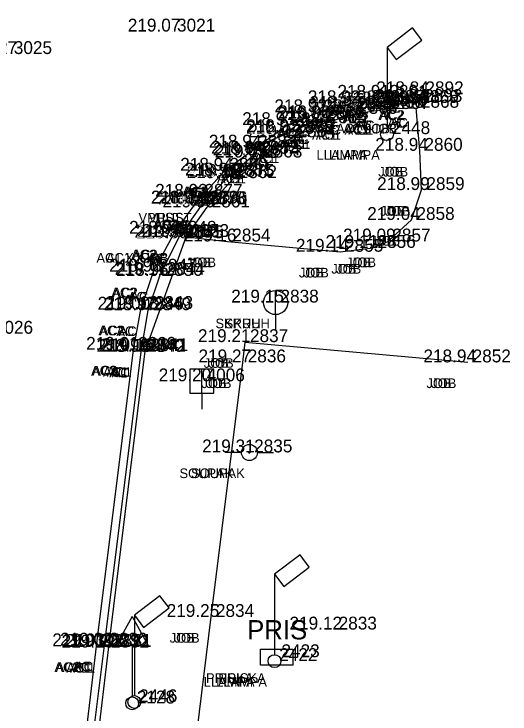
# Model space of a CAD drawing. Extents: x -471047 to -470889, y -1102859 to -1102000.
# Drawn here: x -470921.79 to -470906.35, y -1102184.25 to -1102162.47 of the extents above; entities that cross this region are included whole.
import ezdxf

# ---------------------------------------------------------------- set-up
doc = ezdxf.new("R2010")
doc.units = 0
for name, color, linetype in [('Vrstva 1', 7, 'Continuous'), ('Vrstva 11', 7, 'Continuous'), ('Vrstva 19', 7, 'Continuous'), ('Vrstva 23', 7, 'Continuous'), ('Vrstva 25', 7, 'Continuous'), ('Vrstva 30', 7, 'Continuous'), ('Vrstva 34', 7, 'Continuous'), ('Vrstva 35', 7, 'Continuous'), ('Vrstva 36', 7, 'Continuous'), ('Vrstva 38', 7, 'Continuous'), ('Vrstva 5', 7, 'Continuous'), ('Vrstva 7', 7, 'Continuous'), ('Vrstva 8', 7, 'Continuous')]:
    doc.layers.add(name, color=color, linetype=linetype)

msp = doc.modelspace()

# ---------------------------------------------------------------- linework, layer by layer
at = {"layer": 'Vrstva 1'}
for points in [[(-471040.344, -1102858.385), (-471031.676, -1102846.187), (-471026.357, -1102838.629), (-471023.212, -1102833.975), (-471019.21, -1102827.465), (-471016.861, -1102823.272), (-471013.099, -1102815.912), (-471010.824, -1102810.955), (-471007.329, -1102802.292), (-471005.34, -1102796.515), (-471002.842, -1102787.838), (-471001.3, -1102780.997), (-471000.19, -1102774.713), (-470999.247, -1102768.204), (-470998.794, -1102764.784), (-470997.199, -1102751.812), (-470994.899, -1102732.807), (-470992.551, -1102713.262), (-470990.326, -1102694.887), (-470988.122, -1102676.57), (-470985.812, -1102657.305), (-470983.537, -1102638.407), (-470981.386, -1102620.622), (-470979.843, -1102608.014), (-470976.377, -1102579.253), (-470972.945, -1102550.69), (-470970.475, -1102530.206), (-470967.905, -1102508.801), (-470965.053, -1102485.131), (-470962.734, -1102465.9), (-470960.173, -1102444.812), (-470957.795, -1102425.103), (-470954.965, -1102401.839), (-470953.834, -1102392.574), (-470952.33, -1102379.985), (-470950.744, -1102366.853), (-470948.978, -1102352.106), (-470947.037, -1102335.844), (-470944.949, -1102318.462), (-470944.013, -1102310.745), (-470942.39, -1102297.267), (-470939.519, -1102273.45), (-470937.593, -1102257.43), (-470936.064, -1102244.81), (-470934.114, -1102228.634), (-470931.621, -1102207.856), (-470929.536, -1102190.857), (-470926.572, -1102166.31), (-470924.91, -1102152.663), (-470923.413, -1102140.333), (-470921.923, -1102127.669), (-470921.155, -1102120.084), (-470920.446, -1102109.574), (-470919.912, -1102099.137), (-470919.63, -1102088.981), (-470919.523, -1102081.193), (-470919.563, -1102070.395), (-470919.714, -1102064.236), (-470920.134, -1102054.704), (-470920.462, -1102047.615), (-470920.599, -1102044.52), (-470920.743, -1102041.873), (-470921.125, -1102034.455), (-470921.774, -1102030.337), (-470922.418, -1102027.787), (-470923.734, -1102023.93), (-470924.872, -1102021.434), (-470926.752, -1102018.182), (-470927.953, -1102016.45), (-470929.616, -1102014.424), (-470932.252, -1102011.756), (-470935.111, -1102009.425), (-470938.391, -1102007.371), (-470942.651, -1102005.401)], [(-471041.328, -1102857.18), (-471032.144, -1102844.242), (-471027.583, -1102837.763), (-471024.388, -1102833.028), (-471020.451, -1102826.6), (-471018.089, -1102822.378), (-471014.542, -1102815.445), (-471012.233, -1102810.418), (-471009.247, -1102803.108), (-471006.795, -1102796.098), (-471004.315, -1102787.532), (-471002.782, -1102780.723), (-471001.674, -1102774.458), (-471000.75, -1102768.095), (-471000.28, -1102764.601), (-470998.692, -1102751.741), (-470996.378, -1102732.635), (-470994.028, -1102713.058), (-470991.808, -1102694.749), (-470989.616, -1102676.447), (-470987.284, -1102657.013), (-470985.031, -1102638.272), (-470982.87, -1102620.431), (-470981.334, -1102607.933), (-470977.881, -1102579.263), (-470974.429, -1102550.492), (-470971.964, -1102530.054), (-470969.391, -1102508.607), (-470966.54, -1102484.984), (-470964.231, -1102465.853), (-470961.679, -1102444.752), (-470959.304, -1102425.078), (-470956.455, -1102401.634), (-470955.339, -1102392.489), (-470953.812, -1102379.71), (-470952.249, -1102366.808), (-470950.479, -1102352.023), (-470948.536, -1102335.868), (-470946.426, -1102318.233), (-470945.493, -1102310.531), (-470943.864, -1102297.013), (-470940.984, -1102273.071), (-470939.078, -1102257.195), (-470937.559, -1102244.684), (-470935.592, -1102228.353), (-470933.101, -1102207.653), (-470931.011, -1102190.57), (-470928.046, -1102166.021), (-470926.409, -1102152.578), (-470924.898, -1102140.121), (-470923.427, -1102127.544), (-470922.647, -1102119.826), (-470921.919, -1102109.229), (-470921.42, -1102099.134), (-470921.127, -1102089.016), (-470921.023, -1102081.453), (-470921.061, -1102070.468), (-470921.209, -1102064.314), (-470921.666, -1102053.966), (-470922.156, -1102043.345), (-470922.299, -1102039.934), (-470922.637, -1102034.36), (-470923.091, -1102031.241), (-470923.847, -1102028.247), (-470925.083, -1102024.594), (-470926.222, -1102022.086), (-470928.04, -1102018.943), (-470929.138, -1102017.357), (-470930.929, -1102015.175), (-470933.062, -1102013.049), (-470936.379, -1102010.368), (-470939.169, -1102008.662), (-470942.899, -1102006.906), (-470945.661, -1102005.908)]]:
    msp.add_spline(points, degree=3, dxfattribs=at)
at = {"layer": 'Vrstva 11'}
for p, q in [((-470914.708, -1102176.114), (-470915.208, -1102176.114)), ((-470914.208, -1102176.114), (-470913.708, -1102176.114))]:
    msp.add_line(p, q, dxfattribs=at)
for radius in [0.25, 0.025]:
    msp.add_circle((-470914.458, -1102176.114), radius, dxfattribs=at)
at = {"layer": 'Vrstva 19'}
for p, q in [((-470918.107, -1102181.215), (-470918.607, -1102182.115)), ((-470918.107, -1102181.215), (-470917.607, -1102182.115)), ((-470917.607, -1102182.115), (-470918.607, -1102182.115)), ((-470918.107, -1102182.115), (-470918.107, -1102183.715))]:
    msp.add_line(p, q, dxfattribs=at)
msp.add_circle((-470918.107, -1102183.915), 0.2, dxfattribs=at)
at = {"layer": 'Vrstva 23'}
for p, q in [((-470909.38, -1102162.908), (-470910.175, -1102163.513)), ((-470909.09, -1102163.286), (-470909.38, -1102162.908)), ((-470909.888, -1102163.89), (-470909.09, -1102163.286)), ((-470910.175, -1102163.513), (-470910.175, -1102166.013)), ((-470910.175, -1102163.513), (-470909.888, -1102163.89)), ((-470912.884, -1102179.298), (-470913.679, -1102179.903)), ((-470912.594, -1102179.676), (-470912.884, -1102179.298)), ((-470913.392, -1102180.28), (-470912.594, -1102179.676)), ((-470913.679, -1102179.903), (-470913.679, -1102182.403)), ((-470913.679, -1102179.903), (-470913.392, -1102180.28)), ((-470917.245, -1102180.571), (-470918.04, -1102181.176)), ((-470916.955, -1102180.948), (-470917.245, -1102180.571)), ((-470917.752, -1102181.554), (-470916.955, -1102180.948)), ((-470918.04, -1102181.176), (-470918.04, -1102183.676)), ((-470918.04, -1102181.176), (-470917.752, -1102181.554))]:
    msp.add_line(p, q, dxfattribs=at)
msp.add_lwpolyline([(-470914.109, -1102182.231), (-470913.109, -1102182.231), (-470913.109, -1102182.731), (-470914.109, -1102182.731)], close=True, dxfattribs=at)
for centre in [(-470910.175, -1102166.213), (-470913.679, -1102182.603), (-470918.04, -1102183.876)]:
    msp.add_circle(centre, 0.2, dxfattribs=at)
at = {"layer": 'Vrstva 25'}
for p, q in [((-470916.26, -1102167.91), (-470916.26, -1102168.41)), ((-470915.76, -1102167.91), (-470916.26, -1102167.91)), ((-470915.76, -1102168.41), (-470915.76, -1102167.91)), ((-470916.26, -1102168.16), (-470915.76, -1102168.16)), ((-470916.26, -1102168.41), (-470915.76, -1102168.41)), ((-470913.643, -1102171.824), (-470913.643, -1102171.074)), ((-470913.643, -1102171.824), (-470913.643, -1102172.324))]:
    msp.add_line(p, q, dxfattribs=at)
msp.add_circle((-470913.643, -1102171.449), 0.375, dxfattribs=at)
at = {"layer": 'Vrstva 30'}
for p, q in [((-470916.315, -1102173.521), (-470916.315, -1102174.271)), ((-470915.565, -1102173.521), (-470916.315, -1102173.521)), ((-470915.94, -1102174.271), (-470915.94, -1102173.521)), ((-470915.565, -1102174.271), (-470915.565, -1102173.521)), ((-470916.315, -1102174.271), (-470915.565, -1102174.271)), ((-470915.94, -1102174.271), (-470915.94, -1102174.771))]:
    msp.add_line(p, q, dxfattribs=at)
at = {"layer": 'Vrstva 34'}
for p, q in [((-470916.86, -1102163.02), (-470916.86, -1102163.02)), ((-470910.25, -1102165.08), (-470910.25, -1102165.08)), ((-470909.13, -1102164.97), (-470909.13, -1102164.97)), ((-470911.26, -1102165.25), (-470911.26, -1102165.25)), ((-470910.21, -1102165.29), (-470910.21, -1102165.29)), ((-470909.28, -1102165.24), (-470909.28, -1102165.24)), ((-470909.17, -1102165.21), (-470909.17, -1102165.21)), ((-470912.3, -1102165.53), (-470912.3, -1102165.53)), ((-470911.26, -1102165.49), (-470911.26, -1102165.49)), ((-470911.25, -1102165.43), (-470911.25, -1102165.43)), ((-470910.25, -1102165.34), (-470910.25, -1102165.34)), ((-470910.18, -1102165.43), (-470910.18, -1102165.43)), ((-470909.27, -1102165.39), (-470909.27, -1102165.39)), ((-470912.22, -1102165.72), (-470912.22, -1102165.72)), ((-470911.19, -1102165.58), (-470911.19, -1102165.58)), ((-470913.3, -1102165.93), (-470913.3, -1102165.93)), ((-470912.21, -1102165.77), (-470912.21, -1102165.77)), ((-470912.14, -1102165.87), (-470912.14, -1102165.87)), ((-470913.18, -1102166.15), (-470913.18, -1102166.15)), ((-470913.18, -1102166.2), (-470913.18, -1102166.2)), ((-470913.11, -1102166.31), (-470913.11, -1102166.31)), ((-470910.17, -1102166.21), (-470910.17, -1102166.21)), ((-470914.34, -1102166.63), (-470914.34, -1102166.63)), ((-470914.27, -1102166.82), (-470914.27, -1102166.82)), ((-470909.16, -1102166.73), (-470909.16, -1102166.73)), ((-470914.21, -1102166.87), (-470914.21, -1102166.87)), ((-470914.15, -1102166.94), (-470914.15, -1102166.94)), ((-470915.23, -1102167.35), (-470915.23, -1102167.35)), ((-470915.08, -1102167.5), (-470915.08, -1102167.5)), ((-470915.02, -1102167.54), (-470915.02, -1102167.54)), ((-470914.94, -1102167.58), (-470914.94, -1102167.58)), ((-470909.1, -1102167.95), (-470909.1, -1102167.95)), ((-470916.01, -1102168.16), (-470916.01, -1102168.16)), ((-470916.14, -1102168.37), (-470916.14, -1102168.37)), ((-470915.92, -1102168.39), (-470915.92, -1102168.39)), ((-470915.86, -1102168.39), (-470915.86, -1102168.39)), ((-470915.78, -1102168.49), (-470915.78, -1102168.49)), ((-470909.41, -1102168.88), (-470909.41, -1102168.88)), ((-470916.82, -1102169.31), (-470916.82, -1102169.31)), ((-470916.65, -1102169.43), (-470916.65, -1102169.43)), ((-470916.6, -1102169.45), (-470916.6, -1102169.45)), ((-470916.43, -1102169.41), (-470916.43, -1102169.41)), ((-470915.14, -1102169.55), (-470915.14, -1102169.55)), ((-470910.16, -1102169.55), (-470910.16, -1102169.55)), ((-470911.63, -1102169.87), (-470911.63, -1102169.87)), ((-470910.62, -1102169.75), (-470910.62, -1102169.75)), ((-470917.44, -1102170.49), (-470917.44, -1102170.49)), ((-470917.25, -1102170.62), (-470917.25, -1102170.62)), ((-470917.18, -1102170.59), (-470917.18, -1102170.59)), ((-470913.64, -1102171.45), (-470913.64, -1102171.45)), ((-470917.84, -1102171.67), (-470917.84, -1102171.67)), ((-470917.61, -1102171.69), (-470917.61, -1102171.69)), ((-470917.55, -1102171.65), (-470917.55, -1102171.65)), ((-470914.59, -1102172.68), (-470914.59, -1102172.68)), ((-470918.07, -1102172.92), (-470918.07, -1102172.92)), ((-470917.83, -1102172.98), (-470917.83, -1102172.98)), ((-470917.78, -1102172.98), (-470917.78, -1102172.98)), ((-470917.7, -1102172.96), (-470917.7, -1102172.96)), ((-470914.66, -1102173.31), (-470914.66, -1102173.31)), ((-470907.66, -1102173.31), (-470907.66, -1102173.31)), ((-470915.94, -1102173.9), (-470915.94, -1102173.9)), ((-470914.46, -1102176.11), (-470914.46, -1102176.11)), ((-470915.65, -1102181.23), (-470915.65, -1102181.23)), ((-470911.83, -1102181.62), (-470911.83, -1102181.62)), ((-470919.21, -1102182.14), (-470919.21, -1102182.14)), ((-470918.97, -1102182.12), (-470918.97, -1102182.12)), ((-470918.92, -1102182.18), (-470918.92, -1102182.18)), ((-470918.84, -1102182.16), (-470918.84, -1102182.16)), ((-470913.61, -1102182.48), (-470913.61, -1102182.48)), ((-470913.68, -1102182.6), (-470913.68, -1102182.6)), ((-470918.11, -1102183.92), (-470918.11, -1102183.92)), ((-470918.04, -1102183.88), (-470918.04, -1102183.88))]:
    msp.add_line(p, q, dxfattribs=at)
at = {"layer": 'Vrstva 5'}
for p, q in [((-470911.264, -1102165.246), (-470910.253, -1102165.079)), ((-470910.253, -1102165.079), (-470909.133, -1102164.966)), ((-470912.296, -1102165.528), (-470911.264, -1102165.246)), ((-470913.297, -1102165.93), (-470912.296, -1102165.528)), ((-470915.228, -1102167.346), (-470913.297, -1102165.93)), ((-470916.135, -1102168.374), (-470915.228, -1102167.346)), ((-470916.815, -1102169.312), (-470916.135, -1102168.374)), ((-470917.441, -1102170.486), (-470916.815, -1102169.312)), ((-470917.841, -1102171.668), (-470917.441, -1102170.486)), ((-470918.07, -1102172.916), (-470917.841, -1102171.668)), ((-470919.213, -1102182.137), (-470918.07, -1102172.916)), ((-470920.841, -1102195.544), (-470919.213, -1102182.137))]:
    msp.add_line(p, q, dxfattribs=at)
at = {"layer": 'Vrstva 7'}
for p, q in [((-470911.193, -1102165.584), (-470910.181, -1102165.426)), ((-470910.181, -1102165.426), (-470909.267, -1102165.391)), ((-470912.137, -1102165.873), (-470911.193, -1102165.584)), ((-470913.114, -1102166.306), (-470912.137, -1102165.873)), ((-470914.145, -1102166.937), (-470913.114, -1102166.306)), ((-470914.939, -1102167.582), (-470914.145, -1102166.937)), ((-470915.778, -1102168.486), (-470914.939, -1102167.582)), ((-470916.426, -1102169.408), (-470915.778, -1102168.486)), ((-470917.7, -1102172.959), (-470916.426, -1102169.408)), ((-470918.838, -1102182.155), (-470917.7, -1102172.959)), ((-470920.454, -1102195.728), (-470918.838, -1102182.155))]:
    msp.add_line(p, q, dxfattribs=at)
at = {"layer": 'Vrstva 8'}
for p, q in [((-470911.249, -1102165.43), (-470910.209, -1102165.291)), ((-470910.209, -1102165.291), (-470909.174, -1102165.213)), ((-470912.224, -1102165.724), (-470911.249, -1102165.43)), ((-470909.155, -1102166.732), (-470909.267, -1102165.391)), ((-470913.182, -1102166.148), (-470912.224, -1102165.724)), ((-470914.337, -1102166.628), (-470913.182, -1102166.148)), ((-470915.077, -1102167.5), (-470914.266, -1102166.818)), ((-470914.266, -1102166.818), (-470914.337, -1102166.628)), ((-470909.103, -1102167.948), (-470909.155, -1102166.732)), ((-470915.918, -1102168.385), (-470915.077, -1102167.5)), ((-470909.412, -1102168.875), (-470909.103, -1102167.948)), ((-470916.65, -1102169.431), (-470915.918, -1102168.385)), ((-470910.155, -1102169.55), (-470909.412, -1102168.875)), ((-470917.246, -1102170.618), (-470916.65, -1102169.431)), ((-470916.426, -1102169.408), (-470915.138, -1102169.551)), ((-470915.138, -1102169.551), (-470911.632, -1102169.869)), ((-470910.616, -1102169.747), (-470910.155, -1102169.55)), ((-470911.632, -1102169.869), (-470910.616, -1102169.747)), ((-470917.61, -1102171.692), (-470917.246, -1102170.618)), ((-470917.828, -1102172.984), (-470917.61, -1102171.692)), ((-470914.665, -1102173.314), (-470914.586, -1102172.677)), ((-470914.586, -1102172.677), (-470907.658, -1102173.307)), ((-470918.971, -1102182.117), (-470917.828, -1102172.984)), ((-470915.653, -1102181.23), (-470914.665, -1102173.314)), ((-470917.47, -1102196.176), (-470915.653, -1102181.23)), ((-470920.651, -1102195.695), (-470918.971, -1102182.117))]:
    msp.add_line(p, q, dxfattribs=at)

# ---------------------------------------------------------------- texts
at = {"layer": 'Vrstva 23'}
msp.add_text('PRIS', height=0.6, dxfattribs=at).set_placement((-470914.53, -1102181.928))
at = {"layer": 'Vrstva 35'}
for s, p in [('AC2', (-470910.446, -1102165.77)), ('AC2', (-470910.405, -1102165.77)), ('AC2', (-470912.576, -1102166.05)), ('AC2', (-470912.535, -1102166.05)), ('AC2', (-470911.566, -1102165.88)), ('AC2', (-470911.525, -1102165.88)), ('AC', (-470910.159, -1102166.01)), ('AC', (-470910.084, -1102166.01)), ('AC', (-470912.239, -1102166.23)), ('AC', (-470912.164, -1102166.23)), ('AC1 JOB', (-470911.759, -1102166.19)), ('AC1 JOB', (-470911.534, -1102166.19)), ('AC1', (-470911.497, -1102166.23)), ('AC1', (-470911.38, -1102166.23)), ('AC', (-470911.199, -1102166.09)), ('AC', (-470911.124, -1102166.09)), ('AC2', (-470913.616, -1102166.33)), ('AC2', (-470913.575, -1102166.33)), ('AC1', (-470912.507, -1102166.38)), ('AC1', (-470912.39, -1102166.38)), ('AC1', (-470913.457, -1102166.67)), ('AC1', (-470913.34, -1102166.67)), ('AC', (-470913.209, -1102166.52)), ('AC', (-470913.134, -1102166.52)), ('AC2', (-470914.616, -1102166.73)), ('AC2', (-470914.575, -1102166.73)), ('AC1', (-470914.427, -1102167.11)), ('AC1', (-470914.31, -1102167.11)), ('AC', (-470914.169, -1102166.95)), ('AC', (-470914.094, -1102166.95)), ('LLAMPA', (-470912.37, -1102167.01)), ('LLAMPA', (-470911.984, -1102167.01)), ('AC', (-470915.329, -1102167.43)), ('AC', (-470915.254, -1102167.43)), ('JOB', (-470910.449, -1102167.53)), ('JOB', (-470910.299, -1102167.53)), ('AC1', (-470915.467, -1102167.74)), ('AC1', (-470915.35, -1102167.74)), ('AC', (-470915.259, -1102167.62)), ('AC', (-470915.184, -1102167.62)), ('AC2', (-470916.546, -1102168.15)), ('AC2', (-470916.505, -1102168.15)), ('AC1', (-470916.257, -1102168.38)), ('AC1', (-470916.14, -1102168.38)), ('AC', (-470916.069, -1102168.3)), ('AC', (-470915.994, -1102168.3)), ('JOB', (-470910.389, -1102168.75)), ('JOB', (-470910.239, -1102168.75)), ('VPUST', (-470917.91, -1102168.96)), ('VPUST', (-470917.599, -1102168.96)), ('AC2', (-470917.456, -1102169.17)), ('AC2', (-470917.415, -1102169.17)), ('AC1', (-470917.097, -1102169.29)), ('AC1', (-470916.98, -1102169.29)), ('AC', (-470916.909, -1102169.19)), ('AC', (-470916.834, -1102169.19)), ('JOB', (-470910.699, -1102169.68)), ('JOB', (-470910.549, -1102169.68)), ('AC2', (-470918.136, -1102170.11)), ('AC2', (-470918.095, -1102170.11)), ('AC1 XJOB', (-470919.219, -1102170.21)), ('AC1 XJOB', (-470918.919, -1102170.21)), ('AC', (-470917.639, -1102170.23)), ('AC', (-470917.564, -1102170.23)), ('JOB', (-470916.429, -1102170.35)), ('JOB', (-470916.279, -1102170.35)), ('JOB', (-470911.449, -1102170.35)), ('JOB', (-470911.299, -1102170.35)), ('JOB', (-470911.909, -1102170.55)), ('JOB', (-470911.759, -1102170.55)), ('JOB', (-470912.919, -1102170.67)), ('JOB', (-470912.769, -1102170.67)), ('AC2', (-470918.756, -1102171.29)), ('AC2', (-470918.715, -1102171.29)), ('AC', (-470918.239, -1102171.42)), ('AC', (-470918.164, -1102171.42)), ('SKRUH', (-470915.515, -1102172.25)), ('SKRUH', (-470915.229, -1102172.25)), ('AC2', (-470919.156, -1102172.47)), ('AC2', (-470919.115, -1102172.47)), ('AC', (-470918.599, -1102172.49)), ('AC', (-470918.524, -1102172.49)), ('JOB', (-470915.879, -1102173.48)), ('JOB', (-470915.729, -1102173.48)), ('AC2', (-470919.386, -1102173.72)), ('AC2', (-470919.345, -1102173.72)), ('AC1', (-470919.017, -1102173.76)), ('AC1', (-470918.9, -1102173.76)), ('AC', (-470918.819, -1102173.78)), ('AC', (-470918.744, -1102173.78)), ('JOB', (-470915.949, -1102174.11)), ('JOB', (-470915.799, -1102174.11)), ('JOB', (-470908.949, -1102174.11)), ('JOB', (-470908.799, -1102174.11)), ('SOUPAK', (-470916.635, -1102176.91)), ('SOUPAK', (-470916.274, -1102176.91)), ('JOB', (-470916.939, -1102182.03)), ('JOB', (-470916.789, -1102182.03)), ('AC2', (-470920.526, -1102182.94)), ('AC2', (-470920.485, -1102182.94)), ('AC1', (-470920.157, -1102182.96)), ('AC1', (-470920.04, -1102182.96)), ('AC', (-470919.959, -1102182.92)), ('AC', (-470919.884, -1102182.92)), ('LLAMPA', (-470915.88, -1102183.4)), ('PRISKA', (-470915.81, -1102183.28)), ('LLAMPA', (-470915.494, -1102183.4)), ('PRISKA', (-470915.424, -1102183.28))]:
    msp.add_text(s, height=0.3, dxfattribs=at).set_placement(p)
at = {"layer": 'Vrstva 36'}
for s, p in [(' 3021', (-470916.86, -1102163.02)), (' 3025', (-470921.94, -1102163.72)), (' 2892', (-470909.13, -1102164.97)), (' 2888', (-470911.26, -1102165.25)), (' 2891', (-470910.25, -1102165.08)), (' 2869', (-470909.28, -1102165.24)), (' 2893', (-470909.17, -1102165.21)), (' 2871', (-470911.26, -1102165.49)), (' 2889', (-470911.25, -1102165.43)), (' 2870', (-470910.25, -1102165.34)), (' 2890', (-470910.21, -1102165.29)), (' 2867', (-470910.18, -1102165.43)), (' 2868', (-470909.27, -1102165.39)), (' 2887', (-470912.3, -1102165.53)), (' 2886', (-470912.22, -1102165.72)), (' 2866', (-470911.19, -1102165.58)), (' 2884', (-470913.3, -1102165.93)), (' 2872', (-470912.21, -1102165.77)), (' 2865', (-470912.14, -1102165.87)), (' 2885', (-470913.18, -1102166.15)), (' 2873', (-470913.18, -1102166.2)), (' 2864', (-470913.11, -1102166.31)), (' 2448', (-470910.17, -1102166.21)), (' 2883', (-470914.34, -1102166.63)), (' 2860', (-470909.16, -1102166.73)), (' 2882', (-470914.27, -1102166.82)), (' 2874', (-470914.21, -1102166.87)), (' 2863', (-470914.15, -1102166.94)), (' 2880', (-470915.23, -1102167.35)), (' 2881', (-470915.08, -1102167.5)), (' 2875', (-470915.02, -1102167.54)), (' 2862', (-470914.94, -1102167.58)), (' 2859', (-470909.1, -1102167.95)), (' 2877', (-470916.01, -1102168.16)), (' 2879', (-470916.14, -1102168.37)), (' 2878', (-470915.92, -1102168.39)), (' 2876', (-470915.86, -1102168.39)), (' 2861', (-470915.78, -1102168.49)), (' 2858', (-470909.41, -1102168.88)), (' 2848', (-470916.82, -1102169.31)), (' 2853', (-470916.43, -1102169.41)), (' 2851', (-470916.65, -1102169.43)), (' 2845', (-470916.6, -1102169.45)), (' 2854', (-470915.14, -1102169.55)), (' 2857', (-470910.16, -1102169.55)), (' 2856', (-470910.62, -1102169.75)), (' 2855', (-470911.63, -1102169.87)), (' 2847', (-470917.44, -1102170.49)), (' 2850', (-470917.25, -1102170.62)), (' 2844', (-470917.18, -1102170.59)), (' 2838', (-470913.64, -1102171.45)), (' 2846', (-470917.84, -1102171.67)), (' 2849', (-470917.61, -1102171.69)), (' 2843', (-470917.55, -1102171.65)), (' 3026', (-470922.53, -1102172.42)), (' 2837', (-470914.59, -1102172.68)), (' 2839', (-470918.07, -1102172.92)), (' 2840', (-470917.83, -1102172.98)), (' 2842', (-470917.78, -1102172.98)), (' 2841', (-470917.7, -1102172.96)), (' 2836', (-470914.66, -1102173.31)), (' 2852', (-470907.66, -1102173.31)), (' 4006', (-470915.94, -1102173.9)), (' 2835', (-470914.46, -1102176.11)), (' 2834', (-470915.65, -1102181.23)), (' 2833', (-470911.83, -1102181.62)), (' 2829', (-470919.21, -1102182.14)), (' 2830', (-470918.97, -1102182.12)), (' 2832', (-470918.92, -1102182.18)), (' 2831', (-470918.84, -1102182.16)), (' 2423', (-470913.61, -1102182.48)), (' 2422', (-470913.68, -1102182.6)), (' 2128', (-470918.11, -1102183.92)), (' 2446', (-470918.04, -1102183.88))]:
    msp.add_text(s, height=0.4, dxfattribs=at).set_placement(p)
at = {"layer": 'Vrstva 38'}
for s, p in [('219.07 ', (-470918.243, -1102163.02)), ('219.27 ', (-470923.323, -1102163.72)), ('218.84 ', (-470910.512, -1102164.97)), ('218.92 ', (-470912.641, -1102165.25)), ('218.91 ', (-470911.72, -1102165.08)), ('218.87 ', (-470910.663, -1102165.24)), ('218.84 ', (-470910.552, -1102165.21)), ('219.02 ', (-470912.641, -1102165.49)), ('218.90 ', (-470912.593, -1102165.43)), ('219.01 ', (-470911.72, -1102165.34)), ('219.01 ', (-470911.65, -1102165.43)), ('218.90 ', (-470911.553, -1102165.29)), ('218.88 ', (-470910.654, -1102165.39)), ('218.92 ', (-470913.681, -1102165.53)), ('218.90 ', (-470913.563, -1102165.72)), ('219.03 ', (-470912.573, -1102165.58)), ('218.93 ', (-470914.683, -1102165.93)), ('219.04 ', (-470913.592, -1102165.77)), ('219.05 ', (-470913.524, -1102165.87)), ('218.92 ', (-470914.561, -1102166.15)), ('219.07 ', (-470914.563, -1102166.2)), ('219.07 ', (-470914.493, -1102166.31)), ('218.94 ', (-470915.722, -1102166.63)), ('218.94 ', (-470910.542, -1102166.73)), ('218.94 ', (-470915.652, -1102166.82)), ('219.09 ', (-470915.594, -1102166.87)), ('219.09 ', (-470915.534, -1102166.94)), ('218.94 ', (-470916.612, -1102167.35)), ('218.95 ', (-470916.464, -1102167.5)), ('219.11 ', (-470916.41, -1102167.58)), ('219.10 ', (-470916.363, -1102167.54)), ('218.99 ', (-470910.484, -1102167.95)), ('218.93 ', (-470917.393, -1102168.16)), ('218.93 ', (-470917.523, -1102168.37)), ('218.94 ', (-470917.302, -1102168.39)), ('219.08 ', (-470917.244, -1102168.39)), ('219.09 ', (-470917.164, -1102168.49)), ('219.04 ', (-470910.792, -1102168.88)), ('218.95 ', (-470918.204, -1102169.31)), ('219.09 ', (-470917.814, -1102169.41)), ('218.94 ', (-470918.032, -1102169.43)), ('219.09 ', (-470917.984, -1102169.45)), ('219.16 ', (-470916.5, -1102169.55)), ('219.09 ', (-470911.544, -1102169.55)), ('219.11 ', (-470912.09, -1102169.75)), ('219.14 ', (-470913.012, -1102169.87)), ('218.98 ', (-470918.824, -1102170.49)), ('219.11 ', (-470918.65, -1102170.59)), ('218.96 ', (-470918.61, -1102170.62)), ('219.15 ', (-470915.024, -1102171.45)), ('219.00 ', (-470919.183, -1102171.67)), ('218.97 ', (-470918.993, -1102171.69)), ('219.13 ', (-470918.933, -1102171.65)), ('219.21 ', (-470916.06, -1102172.68)), ('219.01 ', (-470919.54, -1102172.92)), ('218.99 ', (-470919.214, -1102172.98)), ('219.16 ', (-470919.14, -1102172.98)), ('219.16 ', (-470919.06, -1102172.96)), ('219.27 ', (-470916.043, -1102173.31)), ('218.94 ', (-470909.042, -1102173.31)), ('219.20 ', (-470917.283, -1102173.9)), ('219.31 ', (-470915.93, -1102176.11)), ('219.25 ', (-470917.034, -1102181.23)), ('219.12 ', (-470913.211, -1102181.62)), ('219.03 ', (-470920.593, -1102182.14)), ('219.02 ', (-470920.351, -1102182.12)), ('219.19 ', (-470920.304, -1102182.18)), ('219.20 ', (-470920.183, -1102182.16))]:
    msp.add_text(s, height=0.4, dxfattribs=at).set_placement(p)

doc.saveas('drawing.dxf')
